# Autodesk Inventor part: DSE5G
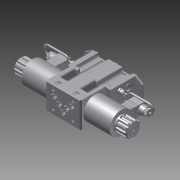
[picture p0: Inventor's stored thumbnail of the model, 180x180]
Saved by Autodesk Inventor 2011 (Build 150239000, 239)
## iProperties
Created: 2012-01
Part Number: DSE5G
Document SubType Name: Modeling
Designer: khramov
Density: 1 g/cm^3
Author: khramov
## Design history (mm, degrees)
derived "DSE5G_C30_10N_E0K11_B.iam"
node "Твердое тело1"
node "0118966.ipt:1"
node "190301.ipt:1"
node "0119383.ipt:1"
sketch "0670792_.ipt:1"
sketch "0119459_CBL_5.ipt:1"
sketch "0672123_.ipt:1"
node "026973.ipt:1"
node "190301.ipt:2"
node "0119383.ipt:2"
sketch "0670792_.ipt:2"
sketch "0119459_CBL_4.ipt:2"
sketch "0672123_.ipt:2"
node "026973.ipt:2"
node "0118964.ipt:1"
node "0118965.ipt:1"
sketch "3001620000.ipt:1"
sketch "0532082_UNI_5931___M3x12.ipt:1"
sketch "0532082_UNI_5931___M3x12.ipt:2"
sketch "0532082_UNI_5931___M3x12.ipt:3"
sketch "0532082_UNI_5931___M3x12.ipt:4"
sketch "0532082_UNI_5931___M3x12.ipt:5"
sketch "0532082_UNI_5931___M3x12.ipt:6"
node "0119458.ipt:1"
sketch "0532140_UNI_5931___M4x16.ipt:1"
sketch "0532140_UNI_5931___M4x16.ipt:2"
sketch "0532140_UNI_5931___M4x16.ipt:3"
sketch "0532140_UNI_5931___M4x16.ipt:4"
sketch "0680013.ipt:1"
sketch "0532085_UNI_5931___M3x8.ipt:1"
sketch "0532085_UNI_5931___M3x8.ipt:2"
sketch "0532085_UNI_5931___M3x8.ipt:3"
sketch "0532085_UNI_5931___M3x8.ipt:4"
sketch "0671857.ipt:1"
node "0119457.ipt:1"
